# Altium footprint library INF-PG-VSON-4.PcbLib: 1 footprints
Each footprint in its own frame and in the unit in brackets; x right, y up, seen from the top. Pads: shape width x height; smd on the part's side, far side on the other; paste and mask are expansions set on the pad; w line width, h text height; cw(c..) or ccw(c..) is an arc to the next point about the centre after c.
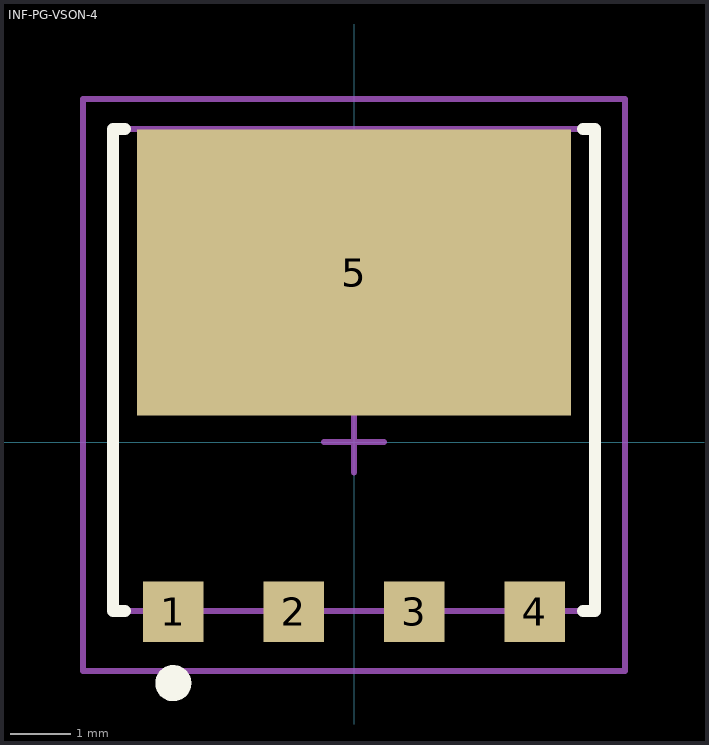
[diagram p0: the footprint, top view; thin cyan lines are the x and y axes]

## INF-PG-VSON-4 [mm] "VSON,2.00mm pitch,8.00mm W X 8.00mm L X 1.1mm H body"
height 1.1
pads (5):
  rect 1x1 smd paste+0 mask+0: 1(-3,-2.815) 2(-1,-2.815) 3(1,-2.815) 4(3,-2.815)
  rect 7.2x4.75 smd paste+0 mask+0: 5(0,2.815)
Top Overlay:
  circle w0.3: c-3,-4 r0.15
  lines w0.2: -3.8,-2.8 -4,-2.8 -4,5.2 -3.8,5.2 ; 3.8,-2.8 4,-2.8 4,5.2 3.8,5.2
Mechanical 3:
  text ".DESIGNATOR" at 0,0 h1.2
Mechanical 13:
  lines w0.1: -4,-2.8 -4,5.2 4,5.2 4,-2.8 -4,-2.8
Mechanical 15:
  lines w0.1: -0.5,0 0.5,0 ; 0,-0.5 0,0.5 ; -4.5,-3.8 -4.5,5.7 4.5,5.7 4.5,-3.8 -4.5,-3.8
3D body: height 1.01, standoff 0, extent -4,-2.8 4,5.2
